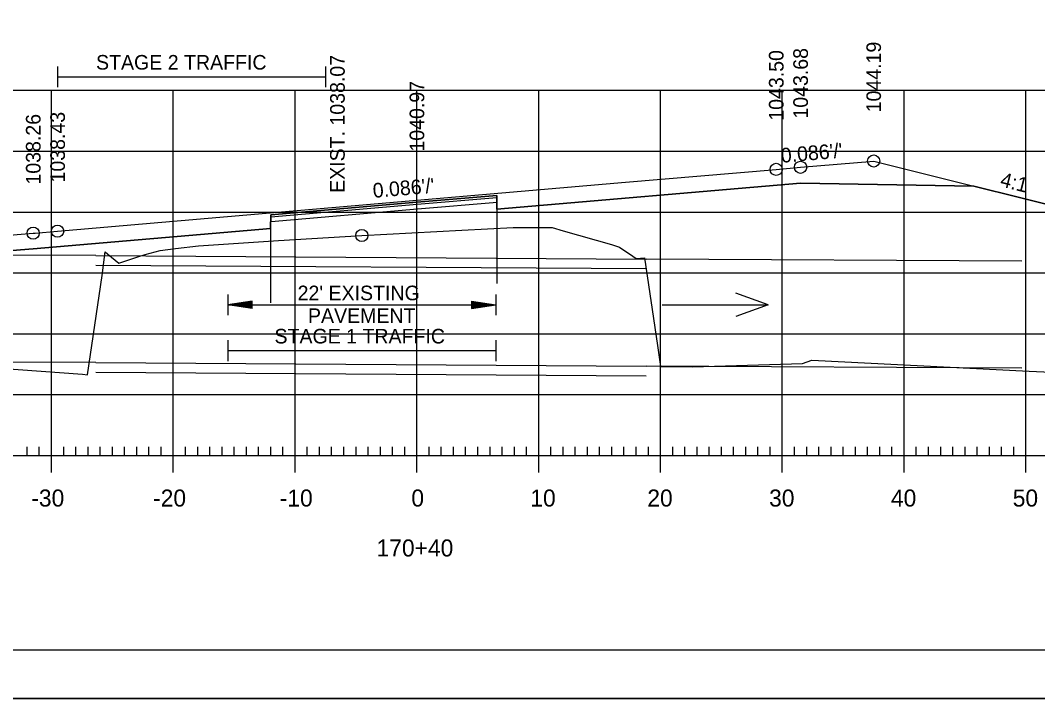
# Model space of a CAD drawing. Extents: x 1322838 to 1324533, y 339903 to 351025.
# Drawn here: x 1323671.2 to 1323754.7, y 346971.9 to 347027.6 of the extents above; entities that cross this region are included whole.
import ezdxf

# ---------------------------------------------------------------- set-up
doc = ezdxf.new("R2010")
doc.units = 0
for name, color, linetype in [('R_Alt Surface', 7, 'Continuous'), ('R_Axis', 7, 'Continuous'), ('R_Axis Annot', 7, 'Continuous'), ('R_Border', 7, 'Continuous'), ('R_Exist Surface', 7, 'Continuous'), ('R_Fin Surface', 7, 'Continuous'), ('R_Fin Surface Annot', 7, 'Continuous'), ('R_Grid', 7, 'Continuous'), ('R_No Plot', 7, 'Continuous'), ('R_Water', 7, 'Continuous'), ('R_Water Annot', 7, 'Continuous'), ('R_Xsect Elev', 7, 'Continuous')]:
    doc.layers.add(name, color=color, linetype=linetype)

msp = doc.modelspace()

# ---------------------------------------------------------------- linework, layer by layer
at = {"layer": 'R_Alt Surface'}
msp.add_lwpolyline([(1323637.719, 347006.063), (1323672.215, 347008.805), (1323691.705, 347010.482), (1323691.715, 347011.607), (1323703.715, 347012.64), (1323710.272, 347013.203), (1323710.282, 347012.078), (1323735.215, 347014.223), (1323749.443, 347013.974)], dxfattribs=at)
at = {"layer": 'R_Axis'}
for p, q in [((1323671.715, 346991.839), (1323671.715, 346992.539)), ((1323672.715, 346991.839), (1323672.715, 346992.539)), ((1323673.715, 346990.439), (1323673.715, 346993.239)), ((1323674.715, 346991.839), (1323674.715, 346992.539)), ((1323675.715, 346991.839), (1323675.715, 346992.539)), ((1323676.715, 346991.839), (1323676.715, 346992.539)), ((1323677.715, 346991.839), (1323677.715, 346992.539)), ((1323678.715, 346991.839), (1323678.715, 346992.539)), ((1323679.715, 346991.839), (1323679.715, 346992.539)), ((1323680.715, 346991.839), (1323680.715, 346992.539)), ((1323681.715, 346991.839), (1323681.715, 346992.539)), ((1323682.715, 346991.839), (1323682.715, 346992.539)), ((1323683.715, 346990.439), (1323683.715, 346993.239)), ((1323684.715, 346991.839), (1323684.715, 346992.539)), ((1323685.715, 346991.839), (1323685.715, 346992.539)), ((1323686.715, 346991.839), (1323686.715, 346992.539)), ((1323687.715, 346991.839), (1323687.715, 346992.539)), ((1323688.715, 346991.839), (1323688.715, 346992.539)), ((1323689.715, 346991.839), (1323689.715, 346992.539)), ((1323690.715, 346991.839), (1323690.715, 346992.539)), ((1323691.715, 346991.839), (1323691.715, 346992.539)), ((1323692.715, 346991.839), (1323692.715, 346992.539)), ((1323693.715, 346990.439), (1323693.715, 346993.239)), ((1323694.715, 346991.839), (1323694.715, 346992.539)), ((1323695.715, 346991.839), (1323695.715, 346992.539)), ((1323696.715, 346991.839), (1323696.715, 346992.539)), ((1323697.715, 346991.839), (1323697.715, 346992.539)), ((1323698.715, 346991.839), (1323698.715, 346992.539)), ((1323699.715, 346991.839), (1323699.715, 346992.539)), ((1323700.715, 346991.839), (1323700.715, 346992.539)), ((1323701.715, 346991.839), (1323701.715, 346992.539)), ((1323702.715, 346991.839), (1323702.715, 346992.539)), ((1323703.715, 346990.439), (1323703.715, 346993.239)), ((1323704.715, 346991.839), (1323704.715, 346992.539)), ((1323705.715, 346991.839), (1323705.715, 346992.539)), ((1323706.715, 346991.839), (1323706.715, 346992.539)), ((1323707.715, 346991.839), (1323707.715, 346992.539)), ((1323708.715, 346991.839), (1323708.715, 346992.539)), ((1323709.715, 346991.839), (1323709.715, 346992.539)), ((1323710.715, 346991.839), (1323710.715, 346992.539)), ((1323711.715, 346991.839), (1323711.715, 346992.539)), ((1323712.715, 346991.839), (1323712.715, 346992.539)), ((1323713.715, 346990.439), (1323713.715, 346993.239)), ((1323714.715, 346991.839), (1323714.715, 346992.539)), ((1323715.715, 346991.839), (1323715.715, 346992.539)), ((1323716.715, 346991.839), (1323716.715, 346992.539)), ((1323717.715, 346991.839), (1323717.715, 346992.539)), ((1323718.715, 346991.839), (1323718.715, 346992.539)), ((1323719.715, 346991.839), (1323719.715, 346992.539)), ((1323720.715, 346991.839), (1323720.715, 346992.539)), ((1323721.715, 346991.839), (1323721.715, 346992.539)), ((1323722.715, 346991.839), (1323722.715, 346992.539)), ((1323723.715, 346990.439), (1323723.715, 346993.239)), ((1323724.715, 346991.839), (1323724.715, 346992.539)), ((1323725.715, 346991.839), (1323725.715, 346992.539)), ((1323726.715, 346991.839), (1323726.715, 346992.539)), ((1323727.715, 346991.839), (1323727.715, 346992.539)), ((1323728.715, 346991.839), (1323728.715, 346992.539)), ((1323729.715, 346991.839), (1323729.715, 346992.539)), ((1323730.715, 346991.839), (1323730.715, 346992.539)), ((1323731.715, 346991.839), (1323731.715, 346992.539)), ((1323732.715, 346991.839), (1323732.715, 346992.539)), ((1323733.715, 346990.439), (1323733.715, 346993.239)), ((1323734.715, 346991.839), (1323734.715, 346992.539)), ((1323735.715, 346991.839), (1323735.715, 346992.539)), ((1323736.715, 346991.839), (1323736.715, 346992.539)), ((1323737.715, 346991.839), (1323737.715, 346992.539)), ((1323738.715, 346991.839), (1323738.715, 346992.539)), ((1323739.715, 346991.839), (1323739.715, 346992.539)), ((1323740.715, 346991.839), (1323740.715, 346992.539)), ((1323741.715, 346991.839), (1323741.715, 346992.539)), ((1323742.715, 346991.839), (1323742.715, 346992.539)), ((1323743.715, 346990.439), (1323743.715, 346993.239)), ((1323744.715, 346991.839), (1323744.715, 346992.539)), ((1323745.715, 346991.839), (1323745.715, 346992.539)), ((1323746.715, 346991.839), (1323746.715, 346992.539)), ((1323747.715, 346991.839), (1323747.715, 346992.539)), ((1323748.715, 346991.839), (1323748.715, 346992.539)), ((1323749.715, 346991.839), (1323749.715, 346992.539)), ((1323750.715, 346991.839), (1323750.715, 346992.539)), ((1323751.715, 346991.839), (1323751.715, 346992.539)), ((1323752.715, 346991.839), (1323752.715, 346992.539)), ((1323753.715, 346990.439), (1323753.715, 346993.239)), ((1323563.715, 346991.839), (1323843.715, 346991.839))]:
    msp.add_line(p, q, dxfattribs=at)
at = {"layer": 'R_Axis Annot'}
for p, q in [((1323674.218, 347023.802), (1323674.218, 347022.096)), ((1323696.218, 347023.802), (1323696.218, 347022.096)), ((1323674.218, 347022.949), (1323696.218, 347022.949)), ((1323688.188, 347005.066), (1323688.188, 347003.361)), ((1323710.188, 347005.066), (1323710.188, 347003.361)), ((1323690.188, 347004.514), (1323688.188, 347004.214)), ((1323690.188, 347003.914), (1323688.188, 347004.214)), ((1323688.188, 347004.214), (1323710.188, 347004.214)), ((1323690.188, 347004.464), (1323688.522, 347004.214)), ((1323690.188, 347003.964), (1323688.522, 347004.214)), ((1323690.188, 347004.413), (1323688.866, 347004.214)), ((1323690.188, 347004.015), (1323688.866, 347004.214)), ((1323690.188, 347004.363), (1323689.199, 347004.214)), ((1323690.188, 347004.065), (1323689.199, 347004.214)), ((1323690.188, 347004.312), (1323689.538, 347004.214)), ((1323690.188, 347004.117), (1323689.538, 347004.214)), ((1323690.188, 347004.261), (1323689.872, 347004.214)), ((1323690.188, 347004.167), (1323689.872, 347004.214)), ((1323690.188, 347003.914), (1323690.188, 347004.514)), ((1323708.188, 347004.514), (1323710.188, 347004.214)), ((1323708.188, 347004.514), (1323708.188, 347003.914)), ((1323708.188, 347004.464), (1323709.854, 347004.214)), ((1323708.188, 347004.413), (1323709.51, 347004.214)), ((1323708.188, 347004.363), (1323709.177, 347004.214)), ((1323708.188, 347004.311), (1323708.838, 347004.214)), ((1323708.188, 347004.261), (1323708.504, 347004.214)), ((1323708.188, 347003.914), (1323710.188, 347004.214)), ((1323708.188, 347004.116), (1323708.838, 347004.214)), ((1323708.188, 347004.015), (1323709.51, 347004.214)), ((1323708.188, 347003.964), (1323709.854, 347004.214)), ((1323708.188, 347004.065), (1323709.177, 347004.214)), ((1323708.188, 347004.167), (1323708.504, 347004.214)), ((1323688.188, 347001.301), (1323688.188, 346999.596)), ((1323710.188, 347001.301), (1323710.188, 346999.596)), ((1323688.188, 347000.449), (1323710.188, 347000.449))]:
    msp.add_line(p, q, dxfattribs=at)
at = {"layer": 'R_Border'}
msp.add_line((1323861.895, 346975.839), (1323545.715, 346975.839), dxfattribs=at)
at = {"layer": 'R_Exist Surface'}
msp.add_lwpolyline([(1323665.668, 346999.295), (1323676.25, 346998.524), (1323676.672, 346998.457), (1323677.878, 347006.631), (1323678.123, 347008.562), (1323678.344, 347008.364), (1323679.245, 347007.643), (1323679.561, 347007.739), (1323680.887, 347008.176), (1323681.4, 347008.344), (1323682.647, 347008.675), (1323683.901, 347008.833), (1323685.769, 347009.068), (1323692.362, 347009.492), (1323699.188, 347009.914), (1323707.411, 347010.359), (1323711.622, 347010.576), (1323714.395, 347010.568), (1323714.807, 347010.567), (1323715.727, 347010.289), (1323719.698, 347009.173), (1323720.354, 347008.945), (1323721.445, 347008.205), (1323721.725, 347008.03), (1323722.395, 347008.078), (1323723.467, 347000.864), (1323723.708, 346999.145), (1323726.33, 346999.13), (1323735.372, 346999.404), (1323736.148, 346999.654), (1323753.976, 346998.769), (1323757.56, 346998.611)], dxfattribs=at)
at = {"layer": 'R_Fin Surface'}
msp.add_lwpolyline([(1323609.152, 347002.957), (1323614.569, 347001.151), (1323618.777, 346999.749), (1323618.778, 346999.749), (1323637.719, 347006.063), (1323644.216, 347008.228), (1323660.27, 347009.215), (1323666.215, 347009.581), (1323670.885, 347009.982), (1323672.215, 347010.097), (1323672.366, 347010.11), (1323674.215, 347010.269), (1323674.218, 347010.269), (1323703.715, 347012.806), (1323720.848, 347014.279), (1323733.215, 347015.343), (1323735.215, 347015.515), (1323741.215, 347016.031), (1323749.443, 347013.974), (1323753.18, 347013.04), (1323763.215, 347010.531)], dxfattribs=at)
at = {"layer": 'R_Grid'}
for p, q in [((1323563.715, 347021.839), (1323843.715, 347021.839)), ((1323673.715, 346991.839), (1323673.715, 347021.839)), ((1323683.715, 346991.839), (1323683.715, 347021.839)), ((1323693.715, 346991.839), (1323693.715, 347021.839)), ((1323703.715, 346991.839), (1323703.715, 347021.839)), ((1323713.715, 346991.839), (1323713.715, 347021.839)), ((1323723.715, 346991.839), (1323723.715, 347021.839)), ((1323733.715, 346991.839), (1323733.715, 347021.839)), ((1323743.715, 346991.839), (1323743.715, 347021.839)), ((1323753.715, 346991.839), (1323753.715, 347021.839)), ((1323563.715, 347016.839), (1323843.715, 347016.839)), ((1323563.715, 347011.839), (1323843.715, 347011.839)), ((1323563.715, 347006.839), (1323843.715, 347006.839)), ((1323563.715, 347001.839), (1323843.715, 347001.839)), ((1323563.715, 346996.839), (1323843.715, 346996.839)), ((1323563.715, 346991.839), (1323843.715, 346991.839))]:
    msp.add_line(p, q, dxfattribs=at)
at = {"layer": 'R_No Plot'}
for p, q in [((1323703.762, 347012.1), (1323710.306, 347012.662)), ((1323691.746, 347011.066), (1323703.762, 347012.1)), ((1323710.282, 347012.078), (1323710.282, 347005.969)), ((1323691.705, 347010.482), (1323691.705, 347004.373)), ((1323533.315, 346971.86), (1323866.648, 346971.86))]:
    msp.add_line(p, q, dxfattribs=at)
for points in [[(1323533.308, 347185.193), (1323866.648, 347185.193), (1323866.648, 346971.856), (1323533.308, 346971.856)], [(1323779.635, 347181.299), (1323799.255, 347181.299), (1323799.255, 347171.419), (1323815.368, 347171.419), (1323838.567, 347171.419), (1323838.567, 347138.748), (1323861.775, 347138.748), (1323861.895, 346975.839), (1323545.715, 346975.839), (1323545.715, 347181.299)]]:
    msp.add_lwpolyline(points, close=True, dxfattribs=at)
for points in [[(1323763.215, 347010.531), (1323753.18, 347013.04), (1323749.443, 347013.974), (1323735.215, 347014.223), (1323710.282, 347012.078), (1323710.272, 347013.203), (1323703.715, 347012.64), (1323691.715, 347011.607), (1323691.705, 347010.482), (1323672.215, 347008.805), (1323637.719, 347006.063)], [(1323691.714, 347011.439), (1323703.73, 347012.474), (1323710.274, 347013.036)], [(1323665.668, 346999.295), (1323676.25, 346998.524), (1323676.672, 346998.457), (1323677.878, 347006.631), (1323678.123, 347008.562), (1323678.344, 347008.364), (1323679.245, 347007.643), (1323679.561, 347007.739), (1323680.887, 347008.176), (1323681.4, 347008.344), (1323682.647, 347008.675), (1323683.901, 347008.833), (1323685.769, 347009.068), (1323692.362, 347009.492), (1323699.188, 347009.914), (1323707.411, 347010.359), (1323711.622, 347010.576), (1323714.395, 347010.568), (1323714.807, 347010.567), (1323715.727, 347010.289), (1323719.698, 347009.173), (1323720.354, 347008.945), (1323721.445, 347008.205), (1323721.725, 347008.03), (1323722.395, 347008.078), (1323723.467, 347000.864), (1323723.708, 346999.145), (1323726.33, 346999.13), (1323735.372, 346999.404), (1323736.148, 346999.654), (1323753.976, 346998.769), (1323757.56, 346998.611)]]:
    msp.add_lwpolyline(points, dxfattribs=at)
for centre in [(1323733.215, 347015.343), (1323735.215, 347015.515), (1323741.215, 347016.031), (1323672.215, 347010.097), (1323674.215, 347010.269), (1323699.188, 347009.914)]:
    msp.add_circle(centre, 0.5, dxfattribs=at)
at = {"layer": 'R_Water'}
for p, q in [((1323677.36, 347008.258), (1323663.37, 347008.34)), ((1323677.36, 347008.258), (1323722.536, 347007.978)), ((1323753.37, 347007.796), (1323722.536, 347007.978)), ((1323677.36, 347007.466), (1323722.536, 347007.186)), ((1323677.36, 346999.466), (1323663.37, 346999.548)), ((1323677.36, 346999.466), (1323722.536, 346999.186)), ((1323753.37, 346999.005), (1323722.536, 346999.186)), ((1323677.36, 346998.674), (1323722.536, 346998.394))]:
    msp.add_line(p, q, dxfattribs=at)
at = {"layer": 'R_Water Annot'}
for p, q in [((1323732.546, 347004.213), (1323729.886, 347005.181)), ((1323723.856, 347004.213), (1323732.546, 347004.213)), ((1323732.546, 347004.213), (1323729.886, 347003.245))]:
    msp.add_line(p, q, dxfattribs=at)

# ---------------------------------------------------------------- texts
at = {"layer": 'R_Axis Annot'}
for s, height, p in [('STAGE 2 TRAFFIC', 1.2, (1323677.371, 347023.54)), ("22' EXISTING ", 1.2, (1323693.921, 347004.589)), ('PAVEMENT', 1.2, (1323694.771, 347002.722)), ('STAGE 1 TRAFFIC', 1.2, (1323692.022, 347001.039)), ('-30', 1.4, (1323672.056, 346987.639)), ('-20', 1.4, (1323682.056, 346987.639)), ('-10', 1.4, (1323692.453, 346987.639)), ('0', 1.4, (1323703.258, 346987.639)), ('10', 1.4, (1323713.026, 346987.639)), ('20', 1.4, (1323722.63, 346987.639)), ('30', 1.4, (1323732.63, 346987.639)), ('40', 1.4, (1323742.63, 346987.639)), ('50', 1.4, (1323752.63, 346987.639)), ('170+40', 1.4, (1323700.403, 346983.539))]:
    msp.add_text(s, height=height, dxfattribs=at).set_placement(p)
at = {"layer": 'R_Fin Surface Annot'}
for s, rotation, p in [('1043.50', 90, (1323733.815, 347019.343)), ('1043.68', 90, (1323735.815, 347019.515)), ('1044.19', 90, (1323741.815, 347020.031)), ('1040.97', 90, (1323704.315, 347016.806)), ('1038.26', 90, (1323672.815, 347014.097)), ('1038.43', 90, (1323674.815, 347014.269)), ("0.086'/'", 4.91544, (1323733.642, 347015.881)), ('4:1', 345.96364, (1323751.53, 347013.967)), ("0.086'/'", 4.91532, (1323700.142, 347013))]:
    msp.add_text(s, height=1.2, rotation=rotation, dxfattribs=at).set_placement(p)
at = {"layer": 'R_Xsect Elev'}
msp.add_text('EXIST. 1038.07', height=1.2, rotation=90, dxfattribs=at).set_placement((1323697.788, 347013.414))

doc.saveas('drawing.dxf')
